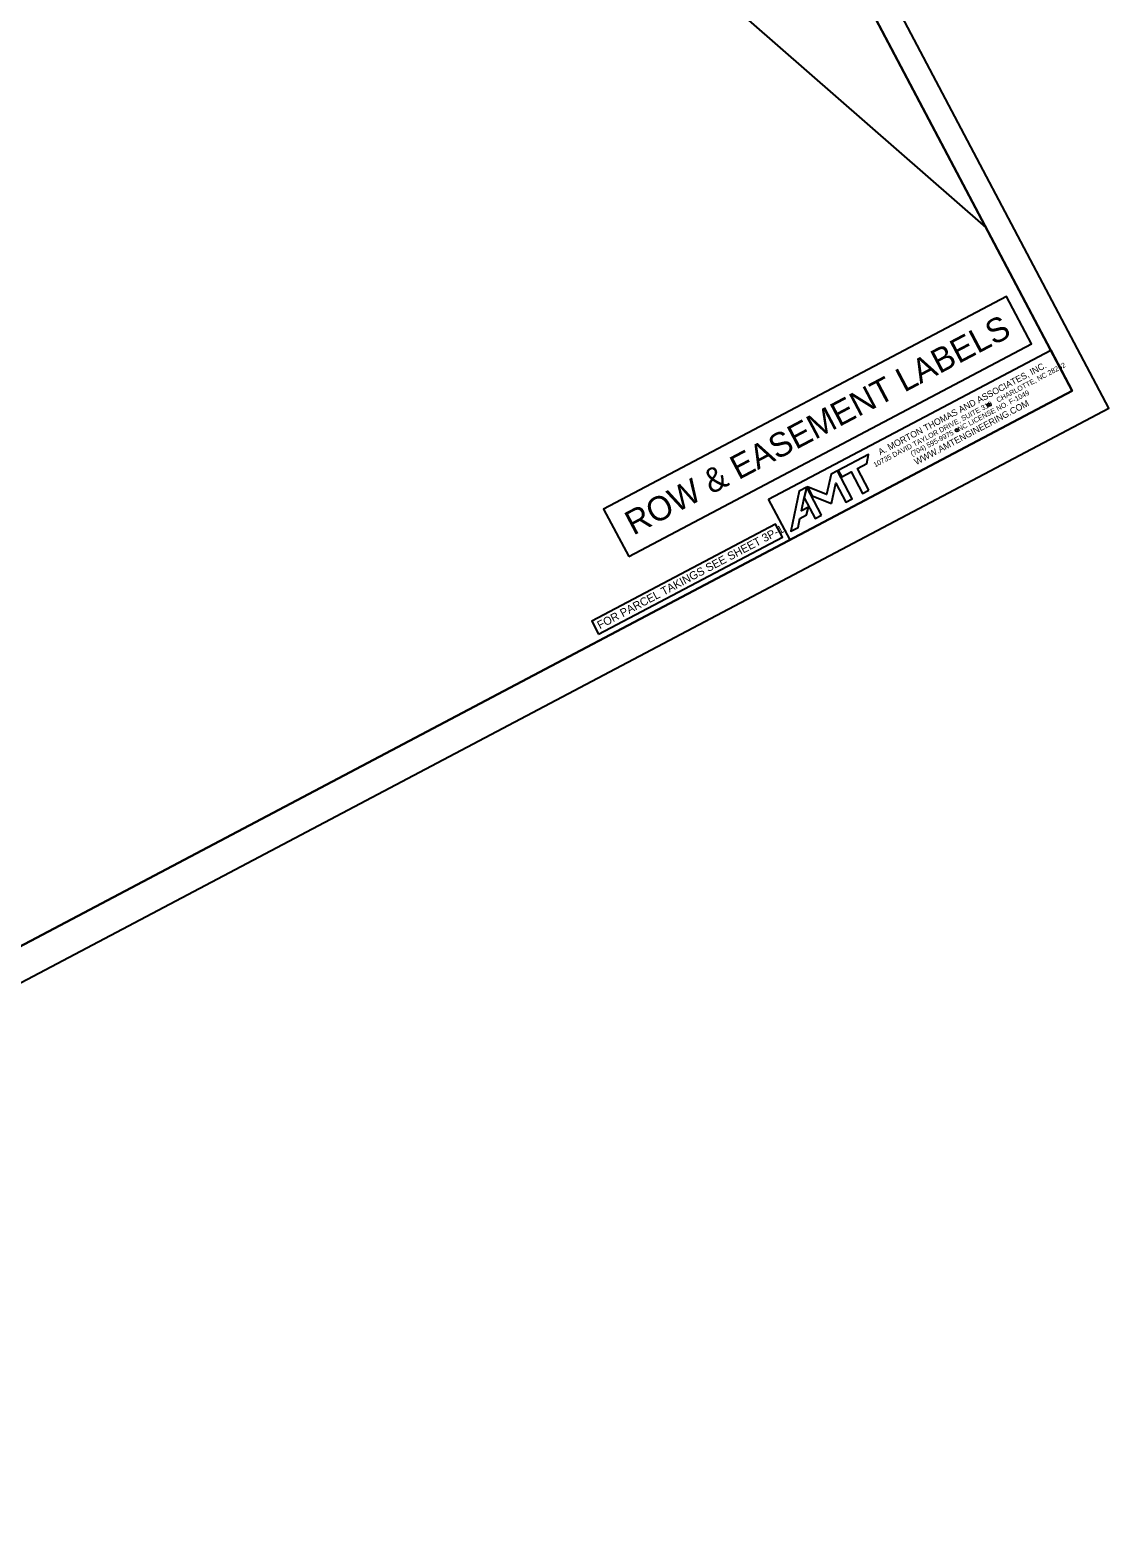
# Model space of a CAD drawing. Extents: x 1486642 to 1489051, y 497560 to 499336.
# Drawn here: x 1488300 to 1489051, y 497582 to 498631 of the extents above; entities that cross this region are included whole.
import ezdxf

# ---------------------------------------------------------------- set-up
doc = ezdxf.new("R2010")
doc.units = 0
for name, color, linetype in [('Prop Grid Mask', 7, 'Continuous'), ('Prop Horizontal Alignment Curve and Spiral Data', 7, 'Continuous'), ('Sheet Block Title CELL', 7, 'Continuous'), ('Sheet Clip Boundary CELL', 7, 'Continuous'), ('Sheet Plan CELL', 7, 'Continuous'), ('Sheet Plot Border Outside CELL', 7, 'Continuous')]:
    doc.layers.add(name, color=color, linetype=linetype)

msp = doc.modelspace()

# ---------------------------------------------------------------- linework, layer by layer
at = {"layer": 'Prop Grid Mask'}
for points in [[(1488716.9, 498264.7), (1488997.2, 498412.7), (1488979.8, 498445.8), (1488699.4, 498297.8)], [(1488814.1, 498304.6), (1489010.5, 498408.3), (1489025.4, 498380), (1488829.1, 498276.3)], [(1488695.9, 498210.7), (1488823.8, 498278.2), (1488818.9, 498287.3), (1488691.1, 498219.8)]]:
    msp.add_lwpolyline(points, close=True, dxfattribs=at)
at = {"layer": 'Sheet Block Title CELL'}
msp.add_lwpolyline([(1488814.1, 498304.6), (1489010.5, 498408.3), (1489025.4, 498380), (1488829.1, 498276.3)], close=True, dxfattribs=at)
for points in [[(1488883.9, 498311), (1488876, 498326), (1488882.5, 498329.4), (1488883.8, 498335.8), (1488862.7, 498324.6), (1488865.1, 498320.2), (1488871.6, 498323.6), (1488879.5, 498308.7), (1488883.9, 498311)], [(1488857.9, 498301.6), (1488861, 498315.8), (1488868, 498302.6), (1488872.4, 498304.9), (1488862.2, 498324.3), (1488857.7, 498322), (1488854.6, 498307.9), (1488841.3, 498313.3), (1488844.6, 498307.1), (1488857.9, 498301.6)], [(1488839, 498305.5), (1488840.7, 498313), (1488835.5, 498310.3), (1488829.7, 498282.4), (1488834.7, 498285), (1488836, 498291.3), (1488840.6, 498293.7), (1488841.9, 498299.1), (1488837.1, 498296.6), (1488839, 498305.5)], [(1488851, 498293.6), (1488840.7, 498313), (1488839, 498305.5), (1488846.5, 498291.3), (1488851, 498293.6)]]:
    msp.add_lwpolyline(points, dxfattribs=at)
for centre in [(1488967.4, 498370.3), (1488945.1, 498352.7)]:
    msp.add_circle(centre, 1, dxfattribs=at)
at = {"layer": 'Sheet Clip Boundary CELL'}
msp.add_lwpolyline([(1487208.7, 498608.1), (1488222.1, 499143.2), (1488965.4, 498493.7), (1489025.4, 498380), (1487698.9, 497679.6)], close=True, dxfattribs=at)
at = {"layer": 'Sheet Plan CELL'}
for points in [[(1488535.1, 499308.5), (1487208.7, 498608.1), (1487698.9, 497679.6), (1489025.4, 498380)], [(1487698.9, 497679.6), (1487208.7, 498608.1), (1488358.2, 499215.1), (1488428.3, 499082.4), (1488605.2, 499175.8), (1489025.4, 498380)]]:
    msp.add_lwpolyline(points, close=True, dxfattribs=at)
at = {"layer": 'Sheet Plot Border Outside CELL'}
msp.add_lwpolyline([(1487562.2, 497582), (1489050.9, 498368), (1488539.7, 499336.3), (1487050.9, 498550.3)], close=True, dxfattribs=at)

# ---------------------------------------------------------------- texts
at = {"layer": 'Prop Horizontal Alignment Curve and Spiral Data'}
for s, height, p in [('ROW & EASEMENT LABELS', 16.875, (1488720.1, 498279.2)), ('FOR PARCEL TAKINGS SEE SHEET 3P-1.', 5.625, (1488696.8, 498214.1))]:
    msp.add_text(s, height=height, rotation=27.8351, dxfattribs=at).set_placement(p)
at = {"layer": 'Sheet Block Title CELL'}
for s, height, p in [('10735 DAVID TAYLOR DRIVE, SUITE 310   CHARLOTTE, NC 28262', 3.5, (1488888.3, 498326.7)), ('A. MORTON THOMAS AND ASSOCIATES, INC.', 4.5, (1488891.9, 498335.1)), ('(704) 595-9975   NC LICENSE NO. F-1049', 3.5, (1488914.1, 498334.4)), ('WWW.AMTENGINEERING.COM', 4.5, (1488917, 498328.3))]:
    msp.add_text(s, height=height, rotation=27.8346, dxfattribs=at).set_placement(p)

doc.saveas('drawing.dxf')
